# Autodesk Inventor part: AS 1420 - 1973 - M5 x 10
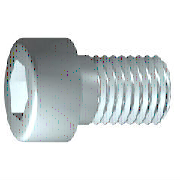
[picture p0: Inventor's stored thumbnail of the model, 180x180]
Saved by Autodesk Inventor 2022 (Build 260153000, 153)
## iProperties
Created: 2021-02
Part Number: AS 1420 - 1973 - M5 x 10
Material: Acciaio, Dolce
Description: Viti con esagono incassato metriche ISO
Document SubType Name: Modeling
Standard: AS 1420 - 1973
Designer: admin
Standards Organization: AS
Language: it-IT
Size Designation: M5 x 10
Categories: <MemberInstance><Categories><Category DisplayName="Elementi di fissaggio" InternalName="e4da775c-781d-43d5-af7c-5136215cf5a6" Mnemonic="FSTN"><Category DisplayN
Density: 7.85 g/cm^3
Appearance: Semilucidato
IsCustomPart: 0
Author: admin
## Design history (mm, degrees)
sketch "Schizzo1"
  geometry: L1 (-1.167, 0)-(10, 0); L2 (10, 0)-(10, 2.5); L3 (10, 2.5)-(2, 2.5); L4 (2, 2.5)-(1.509, 2.5); L5 (1.509, 2.5)-(0, 2.5); L6 (0, 2.5)-(0, 4.25); L7 (0, 4.25)-(-5, 4.25); L8 (-5, 4.25)-(-5, 2.309); L9 (-5, 2.309)-(-2.5, 2.309); L10 (-2.5, 2.309)-(-1.167, 0); L11 (-8, 0)-(13, 0) reference; L12 (0, -0.85)-(0, 5.1) reference; L13 (2, 2.5)-(0, 2.5)
  constraints: 22 end point, 6 parallel, 2 collinear, 2 perpendicular, 1 horizontal, 1 point on line
  dimensions: "d1" = 8 distance from line of L3.end L2 (= GEL); "d2" = 0.49086 distance of L4.end L3.end (computed from GAL); "d3" = 5 distance between parallel lines of L8 L6 (= KOH); "d4" = 2.5 distance of L8.end L9.end (= INTI); "d5" = 60 deg angle of L10 L1; "d6" = 5 diameter of L3 L1 (= GD); "d7" = 5 diameter of L5 L1 (= BDM); "d8" = 4.6188 diameter of L9 L1 (= 1.1547 x SW); "d9" = 8.5 diameter of L7 L1 (= KOD); "d26" = 10 distance between parallel lines of L12 L2 (= NLG)
revolve "Corpo" sketch "Schizzo1" stored, may be unused: angle "d10" = 90 deg
sketch "Schizzo2"
  geometry: L1 (0, -5.95)-(0, 5.95) reference; L2 (-5.95, 0)-(5.95, 0) reference; L3 (2.309, 0)-(1.155, -2); L4 (1.155, -2)-(-1.155, -2); L5 (-1.155, -2)-(-2.309, 0); L6 (-2.309, 0)-(-1.155, 2); L7 (-1.155, 2)-(1.155, 2); L8 (1.155, 2)-(2.309, 0); 2 further points
  constraints: 12 end point, 1 coincident, 1 horizontal alignment, 1 point on line, 12 other
extrude "Intaglio" join sketch "Schizzo2" stored distance "d11" = 10; taper "d12" = 0 deg
workplane "Work Plane1"
fillet "Fillet2" dims "d30" = 0.1 (= R)
body "Solid1"
fillet "Raccordo1" dims "d17" = 0.5 (= RR)
feature "Filettatura" dims "d13" = 8 (= GEL), "d14" = 0
chamfer "Smusso1" distance "d15" = 0.49076 (= -0.5 x SPD + 0.5 x GD); stored, may be unused: second distance "d16" = 0.49076 (= GUL), angle "d27" = 45 deg
other parameters: "GD" = 5 (= NND) [user parameter; used in 2 equation terms], "NLG" = 10 [user parameter; used in 1 equation term], "GEL" = 8 [user parameter; used in 2 equation terms], "KOD" = 8.5 [user parameter; used in 1 equation term], "KOH" = 5 (= NND) [user parameter; used in 1 equation term], "INTI" = 2.5 [user parameter; used in 1 equation term], "GAL" = 0.49076 (= 0.61345 x PTC) [user parameter; used in 1 equation term], "GUL" = 0.49076 (= 0.61345 x PTC) [user parameter; used in 1 equation term], "BDM" = 5 (= NND) [user parameter; used in 1 equation term], "SW" = 4 [user parameter; used in 2 equation terms], "RR" = 0.5 (= 0.1 x NND) [user parameter; used in 1 equation term], "SPD" = 4.01848 (= NND - 1.2269 x PTC) [user parameter; used in 1 equation term], "d19" = 0, "d28" = 0, "d29" = 0, "R" = 0.1 [user parameter; used in 1 equation term], "PHH" = 0.13 [user parameter], "GD1" = 4.01848 (= THREADDIA - 1.2269 x PTC) [user parameter], "THREADDIA" = 5 [user parameter; used in 1 equation term], "FAWI" = 45 deg [user parameter], "TPU" = 12.5 (computed from PTC) [user parameter], "PTC" = 0.8 [user parameter; used in 5 equation terms], "KOH1" = 4.5 [user parameter], "NND" = 5 [user parameter; used in 5 equation terms], "TOA" = 30 deg [user parameter], "E0" = 4.62 (= 1.155 x SW) [user parameter]
